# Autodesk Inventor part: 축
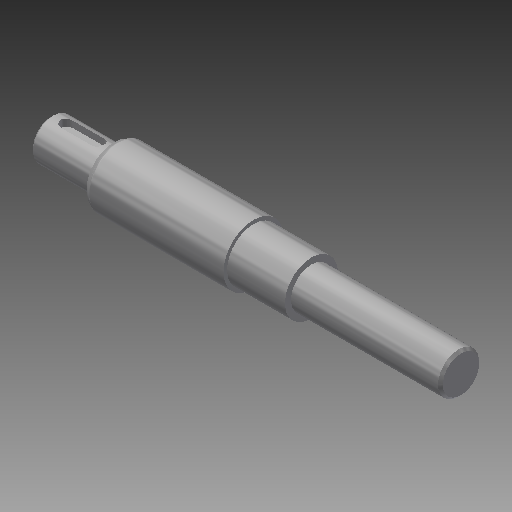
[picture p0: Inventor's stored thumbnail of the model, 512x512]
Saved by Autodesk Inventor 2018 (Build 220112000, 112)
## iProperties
Created: 2019-01
Part Number: 축
Material: 강철, 탄소
Document SubType Name: Modeling
Designer: mduedu
Density: 7.87 g/cm^3
Mass: 452.778 g
Surface Area: 120.904 cm^2
Volume: 57.5322 cm^3
Appearance: 강철
Author: mduedu
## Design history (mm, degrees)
sketch "스케치1"
  geometry: L1 (0, 0)-(26, 0); L2 (26, 0)-(26, 8.5); L3 (26, 8.5)-(0, 8.5); L4 (0, 8.5)-(0, 0); L5 (26, 0)-(84, 0); L6 (84, 0)-(84, 12.5); L7 (84, 12.5)-(26, 12.5); L8 (26, 12.5)-(26, 0); L9 (84, 0)-(108, 0); L10 (108, 0)-(108, 11); L11 (108, 11)-(84, 11); L12 (84, 11)-(84, 0); L13 (108, 0)-(170, 0); L14 (170, 0)-(170, 8.5); L15 (170, 8.5)-(108, 8.5); L16 (108, 8.5)-(108, 0)
  constraints: 32 end point, 8 parallel, 4 horizontal, 4 perpendicular
  dimensions: "d0" = 170 distance between parallel lines of L14 L4; "d2" = 26 distance of L2.end L3.end; "d3" = 24 distance of L10.end L11.end; "d4" = 62 distance of L14.end L15.end; "d5" = 17 diameter of L3 L1; "d6" = 25 diameter of L7 L5; "d7" = 22 diameter of L11 L9; "d8" = 17 diameter of L15 L13
revolve "회전1" sketch "스케치1" stored, may be unused: angle "d9" = 90 deg
node "작업 평면1"
sketch "스케치2" dims "d13" = 18
  geometry: L1 (6.5, -2.5)-(-6.5, -2.5); L2 (-6.5, -2.5)-(-6.5, 2.5); L3 (-6.5, 2.5)-(6.5, 2.5); L4 (6.5, 2.5)-(6.5, -2.5); L5 (13, 8.5)-(13, -8.5) reference; 3 further points
  constraints: 8 end point, 2 midpoint, 2 parallel, 2 vertical alignment, 1 horizontal, 1 horizontal alignment, 1 perpendicular, 4 other
  dimensions: "d10" = 5 distance between parallel lines of L3 L1; "d12" = 4 dimension on L5
extrude "돌출1" cut sketch "스케치2" distance "d14" = 3; taper "d15" = 0 deg
node "작업 평면2"
sketch "스케치3" dims "d19" = 18
  geometry: L1 (-24.5, -2.5)-(-11.5, -2.5); L2 (-11.5, -2.5)-(-11.5, 2.5); L3 (-11.5, 2.5)-(-24.5, 2.5); L4 (-24.5, 2.5)-(-24.5, -2.5); L5 (-31, 8.5)-(-31, -8.5) reference; 3 further points
  constraints: 8 end point, 2 midpoint, 2 parallel, 2 vertical alignment, 1 horizontal, 1 horizontal alignment, 1 perpendicular, 4 other
  dimensions: "d16" = 5 distance between parallel lines of L3 L1; "d18" = 4 dimension on L5
extrude "돌출2" cut sketch "스케치3" distance "d20" = 3; taper "d21" = 0 deg
chamfer "모따기1" distance "d22" = 1; stored, may be unused: second distance "d23" = 2, angle "d24" = 45 deg
chamfer "모따기2" distance "d25" = 2; stored, may be unused: second distance "d26" = 2, angle "d27" = 30 deg
fillet "모깎기2" dims "d30" = 2
node "솔리드1"
